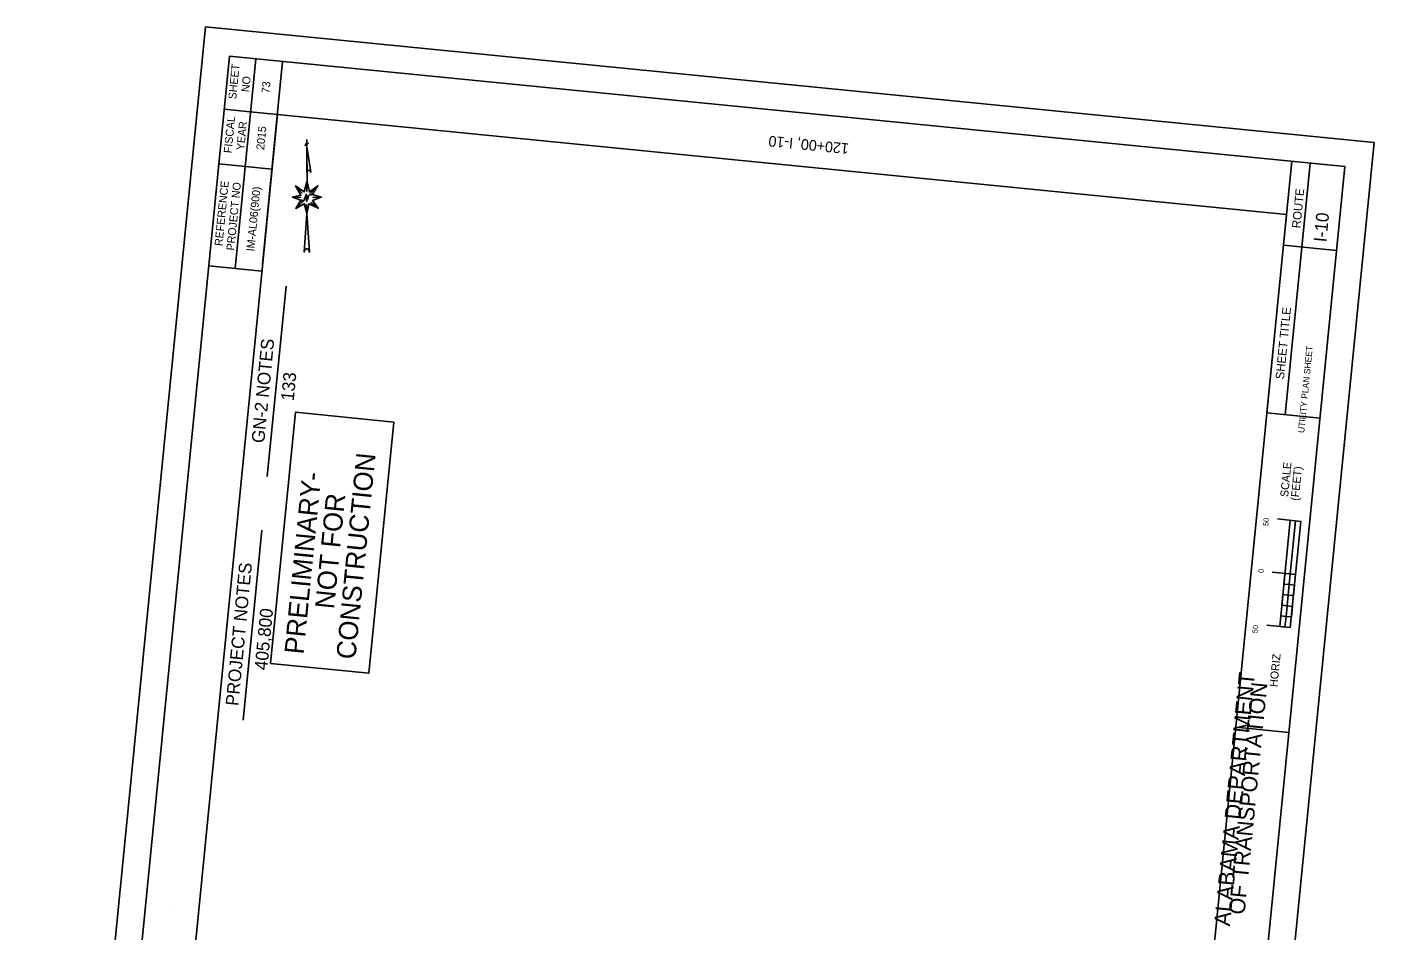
# Model space of a CAD drawing. Extents: x 1796928 to 1798191, y 245238 to 247038.
# Drawn here: x 1796928 to 1798191, y 246192 to 247038 of the extents above; entities that cross this region are included whole.
import ezdxf

# ---------------------------------------------------------------- set-up
doc = ezdxf.new("R2010")
doc.units = 0
for name, color, linetype in [('1', 7, 'Continuous'), ('ANNO-SHT', 7, 'Continuous'), ('ANNO-SYMB', 7, 'Continuous'), ('ANNO-TXT', 7, 'Continuous'), ('CL-CNST', 7, 'Continuous'), ('DRAINAGE', 7, 'Continuous'), ('Level 1', 7, 'Continuous'), ('Level 37', 7, 'Continuous'), ('Level 57', 7, 'Continuous'), ('Level 6', 7, 'Continuous'), ('Level 62', 7, 'Continuous'), ('SHT-BDR', 7, 'Continuous'), ('SHT-BNDRY', 7, 'Continuous')]:
    doc.layers.add(name, color=color, linetype=linetype)

# ---------------------------------------------------------------- blocks, each defined once
blk = doc.blocks.new('SC47208')
at = {"layer": 'Level 1'}
blk.add_line((0, 0), (0, 0), dxfattribs=at)

msp = doc.modelspace()

# ---------------------------------------------------------------- linework, layer by layer
at = {"layer": '1'}
msp.add_lwpolyline([(1797156.7, 246441.4), (1797180, 246676.7), (1797272.2, 246667.6), (1797248.9, 246432.3)], close=True, dxfattribs=at)
at = {"layer": 'ANNO-SYMB'}
for p, q in [((1798122, 246574.6), (1798100.1, 246576.8)), ((1798112, 246575.6), (1798102.2, 246476.1)), ((1798122, 246574.6), (1798112.1, 246475.1)), ((1798122, 246574.6), (1798117, 246575.1)), ((1798122, 246574.6), (1798117, 246575.1)), ((1798122, 246574.6), (1798117, 246575.1)), ((1798117, 246524.9), (1798095.2, 246527.1)), ((1798117, 246524.9), (1798095.2, 246527.1)), ((1798117, 246524.9), (1798095.2, 246527.1)), ((1798112.1, 246525.4), (1798107.1, 246525.9)), ((1798112.1, 246525.4), (1798107.1, 246525.9)), ((1798112.1, 246525.4), (1798107.1, 246525.9)), ((1798112.1, 246525.4), (1798110.1, 246505.5)), ((1798108.1, 246485.6), (1798103.2, 246486.1)), ((1798108.1, 246485.6), (1798103.2, 246486.1)), ((1798112.1, 246475.1), (1798090.2, 246477.3))]:
    msp.add_line(p, q, dxfattribs=at)
for points in [[(1798112.1, 246525.4), (1798117, 246575.1), (1798122, 246574.6), (1798117, 246524.9)], [(1798106.1, 246515.9), (1798107.1, 246525.9), (1798112.1, 246525.4), (1798111.1, 246515.4)], [(1798104.1, 246496), (1798105.1, 246506), (1798110.1, 246505.5), (1798109.1, 246495.5)], [(1798110.1, 246505.5), (1798111.1, 246515.4), (1798116.1, 246514.9), (1798115.1, 246505)], [(1798108.1, 246485.6), (1798109.1, 246495.5), (1798114.1, 246495), (1798113.1, 246485.1)], [(1798102.2, 246476.1), (1798103.2, 246486.1), (1798108.1, 246485.6), (1798107.1, 246475.6)]]:
    msp.add_lwpolyline(points, close=True, dxfattribs=at)
at = {"layer": 'ANNO-TXT'}
for p, q in [((1798122.9, 246831.4), (1798130.7, 246910.1)), ((1798107.4, 246674.5), (1798122.9, 246831.4))]:
    msp.add_line(p, q, dxfattribs=at)
at = {"layer": 'CL-CNST'}
for p, q in [((1797153.6, 246616.6), (1797171.2, 246794.7)), ((1797131, 246388.3), (1797148.6, 246566.4))]:
    msp.add_line(p, q, dxfattribs=at)
at = {"layer": 'Level 57'}
msp.add_line((1797190.8, 246932.2), (1797190.7, 246929.8), dxfattribs=at)
for points in [[(1797191.9, 246928.7), (1797191.8, 246928.6), (1797191.9, 246928.5), (1797192, 246928.6), (1797192, 246928.8), (1797191.7, 246928.8), (1797191.5, 246928.7), (1797191.3, 246928.5), (1797191.1, 246928.2), (1797191, 246927.8), (1797190.8, 246927.2), (1797190.7, 246927), (1797190.6, 246926.6), (1797190.6, 246927.2), (1797190.6, 246928.2), (1797190.4, 246928.8), (1797190.4, 246928.2), (1797190.6, 246926.6), (1797190.6, 246928.2), (1797190.4, 246928.8), (1797190.2, 246928.2), (1797189.9, 246927.2), (1797189.6, 246926.6), (1797189.3, 246926.6), (1797189.1, 246926.6), (1797189, 246926.6), (1797189, 246926.8), (1797189.1, 246926.9), (1797189.2, 246926.9), (1797189.1, 246926.7)], [(1797190.7, 246925.7), (1797194.4, 246901.6), (1797194.2, 246902.3), (1797194, 246902.6), (1797193.6, 246903), (1797193.1, 246903.2), (1797192.8, 246903.3), (1797192.4, 246903.3), (1797192, 246903.3), (1797191.8, 246903.2), (1797191.4, 246903), (1797191.1, 246902.8), (1797190.9, 246902.5), (1797190.8, 246902.2), (1797190.7, 246902.1), (1797190.7, 246925.5), (1797190.9, 246892.6)], [(1797190.8, 246892.6), (1797190.6, 246883.7), (1797190.8, 246892.7), (1797188.1, 246883.1), (1797180.2, 246888.7), (1797186.3, 246882), (1797180.2, 246888.7), (1797185.1, 246880.1), (1797177.1, 246878.2), (1797184.8, 246878), (1797177.3, 246878.3), (1797185, 246875.5), (1797180.4, 246867.7), (1797186.2, 246873.4), (1797180.4, 246867.7), (1797188.3, 246872), (1797190.6, 246863.1), (1797190.5, 246871.5), (1797190.6, 246862.9), (1797192.6, 246871.9), (1797201.6, 246867.8), (1797192.5, 246871.9), (1797190.6, 246862.7), (1797188.3, 246826.7), (1797188.5, 246827.8), (1797188.8, 246828.6), (1797189.3, 246829.1), (1797189.9, 246829.6), (1797190.4, 246829.7), (1797191.1, 246829.7), (1797191.6, 246829.5), (1797192.1, 246829.2), (1797192.5, 246828.7), (1797192.9, 246828), (1797193, 246827.5), (1797193.2, 246826.6), (1797190.7, 246863.2), (1797192.5, 246872), (1797201.4, 246867.8), (1797194.6, 246873.1), (1797201.3, 246868), (1797196.1, 246875), (1797204.1, 246878.1), (1797196.5, 246878), (1797204.4, 246878.1), (1797195.6, 246880.8), (1797201.1, 246888.7), (1797194.6, 246882.3), (1797201.1, 246888.7), (1797193.1, 246883.1), (1797190.9, 246892.5)], [(1797194.6, 246880.6), (1797194.4, 246880.4), (1797194.7, 246880.2), (1797194.9, 246880.5), (1797194.8, 246880.9), (1797194.7, 246881), (1797194, 246880.9), (1797193.4, 246880.7), (1797192.4, 246879.4), (1797192.3, 246879), (1797191.9, 246877.8), (1797191.5, 246876.5), (1797191, 246875.7), (1797190.8, 246874.3), (1797190.8, 246876), (1797190.6, 246878.3), (1797190.5, 246879.5), (1797190, 246880.9), (1797190, 246879.2), (1797190.3, 246876.9), (1797190.5, 246875.5), (1797190.8, 246874.3), (1797190.8, 246876.4), (1797190.6, 246879.5), (1797190, 246880.9), (1797189.7, 246879.4), (1797189.1, 246877.8), (1797188.8, 246877.2), (1797188.5, 246876.3), (1797188.1, 246875.6), (1797187.8, 246875.1), (1797187.6, 246874.5), (1797186.8, 246874.1), (1797186.1, 246874.3), (1797185.9, 246874.5), (1797185.8, 246875.2), (1797186.2, 246875.5), (1797186.5, 246875.2), (1797186.3, 246874.9)]]:
    msp.add_lwpolyline(points, dxfattribs=at)
at = {"layer": 'Level 6'}
for p, q in [((1797142.9, 247007.8), (1797123.5, 246811.5)), ((1797168, 247005.4), (1797149.2, 246815)), ((1797137.6, 246958.1), (1797113.4, 246960.5)), ((1797137.6, 246958.1), (1797163.1, 246955.6)), ((1797133.2, 246906.8), (1797108.3, 246909.3)), ((1798113.4, 246911.8), (1798090.1, 246676.3)), ((1797133.2, 246906.8), (1797158, 246904.4)), ((1797098.9, 246813.9), (1797148.6, 246809))]:
    msp.add_line(p, q, dxfattribs=at)
at = {"layer": 'Level 62'}
msp.add_lwpolyline([(1798023.1, 245237.6), (1798190.5, 246929.3), (1797095.9, 247037.6), (1796928.5, 245345.9)], close=True, dxfattribs=at)
at = {"layer": 'SHT-BDR'}
msp.add_lwpolyline([(1797960.8, 245369.3), (1798108.5, 246862), (1797163.1, 246955.6), (1797015.4, 245462.9)], close=True, dxfattribs=at)
at = {"layer": 'SHT-BNDRY'}
for p, q in [((1798155.4, 246828.2), (1798105.6, 246833.1)), ((1798139.9, 246671.3), (1798090.1, 246676.3)), ((1798110.8, 246376.8), (1798060.9, 246381.7))]:
    msp.add_line(p, q, dxfattribs=at)
msp.add_lwpolyline([(1798004.4, 245302.2), (1798163.2, 246906.9), (1797118.3, 247010.3), (1796959.5, 245405.6)], close=True, dxfattribs=at)

# ---------------------------------------------------------------- block references
at = {"layer": 'DRAINAGE', "xscale": 1.0000020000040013, "yscale": 1.0000020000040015, "rotation": -32.06753455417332}
msp.add_blockref('SC47208', (1797063.6, 246213.4), dxfattribs=at)
msp.add_blockref('SC47208', (1797063.6, 246213.4), dxfattribs=at)

# ---------------------------------------------------------------- texts
at = {"layer": '1'}
for s, p in [('CONSTRUCTION', (1797236.1, 246444.8)), ('PRELIMINARY-', (1797187.6, 246449.6)), ('NOT FOR', (1797216.2, 246492))]:
    msp.add_text(s, height=18, rotation=84.3491, dxfattribs=at).set_placement(p)
at = {"layer": 'ANNO-SHT'}
for s, height, rotation, p in [('73', 7.45, 84.3491, (1797155.6, 246975.2)), ('2015', 7.45, 84.3491, (1797150.7, 246922.2)), ('120+00, I-10', 10, 174.3491, (1797698.9, 246928.4)), ('IM-AL06(900)', 7.449, 84.3491, (1797141.4, 246827.2)), ('  I-10  ', 12, 84.3491, (1798144.9, 246826.8)), ('           UTILITY PLAN SHEET           ', 6, 84.3491, (1798122.7, 246632.7))]:
    msp.add_text(s, height=height, rotation=rotation, dxfattribs=at).set_placement(p)
at = {"layer": 'ANNO-SYMB'}
for s, height, p in [('SCALE', 7.5, (1798110, 246597.1)), ('(FEET)', 7.5, (1798119.9, 246593.6)), (' 50', 5, (1798091.2, 246568.1)), ('0', 5, (1798087, 246526)), ('0', 5, (1798087, 246526)), ('0', 5, (1798087, 246526)), (' 50', 5, (1798081.2, 246467.7)), ('HORIZ', 7.5, (1798100, 246419.2))]:
    msp.add_text(s, height=height, rotation=84.4063, dxfattribs=at).set_placement(p)
at = {"layer": 'ANNO-TXT'}
for s, height, p in [('ROUTE', 8, (1798121.5, 246848.8)), ('SHEET TITLE', 8, (1798106.1, 246707.3)), ('ALABAMA DEPARTMENT', 15, (1798055.5, 246195)), ('OF TRANSPORTATION', 15, (1798069.2, 246205.8))]:
    msp.add_text(s, height=height, rotation=84.3491, dxfattribs=at).set_placement(p)
at = {"layer": 'Level 37'}
for s, p in [('GN-2 NOTES', (1797150.8, 246647.5)), ('133', (1797178.4, 246687)), ('PROJECT NOTES', (1797126.5, 246401.4)), ('405,800', (1797153.6, 246434.8))]:
    msp.add_text(s, height=12, rotation=84.503, dxfattribs=at).set_placement(p)
at = {"layer": 'Level 6'}
for s, p in [('SHEET', (1797124.5, 246969.6)), ('NO', (1797136.7, 246976.3)), ('FISCAL', (1797120.2, 246919.1)), ('YEAR', (1797132, 246921.9)), ('REFERENCE', (1797111.6, 246832.2)), ('PROJECT NO', (1797122.7, 246828))]:
    msp.add_text(s, height=7.44, rotation=84.3491, dxfattribs=at).set_placement(p)

doc.saveas('drawing.dxf')
